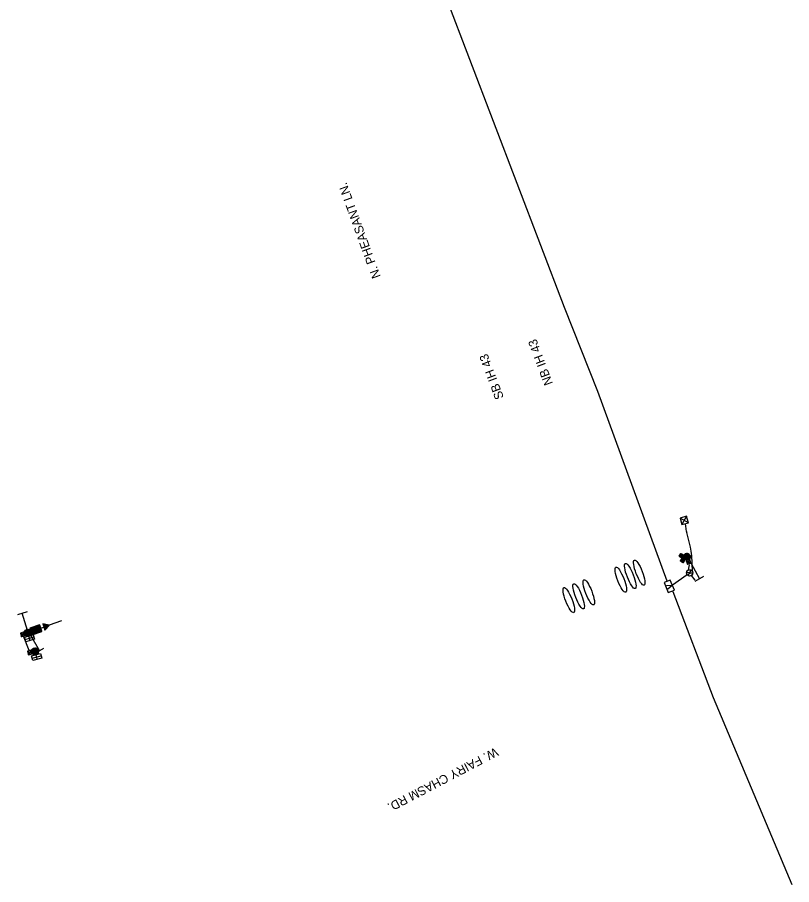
# Model space of a CAD drawing. Extents: x 601562 to 605316, y 332050 to 402250.
# Drawn here: x 602135 to 603050, y 352481 to 353507 of the extents above; entities that cross this region are included whole.
import ezdxf

# ---------------------------------------------------------------- set-up
doc = ezdxf.new("R2010")
doc.units = 0
doc.layers.add('P_FTMS', color=7, linetype='Continuous')
doc.layers.add('P_FTMSConduit', color=7, linetype='Continuous')

# ---------------------------------------------------------------- blocks, each defined once
blk = doc.blocks.new('FTMS_FCV')
at = {"layer": 'P_FTMS'}
blk.add_line((12.7, 16.3), (0.6, -21.9), dxfattribs=at)
blk.add_lwpolyline([(39.1, 24.4), (-39.1, 24.4), (-39.1, -24.4), (39.1, -24.4)], close=True, dxfattribs=at)
blk.add_lwpolyline([(-12.1, 16.2), (0.6, -21.9)], dxfattribs=at)
blk = doc.blocks.new('FMB')
at = {"layer": 'P_FTMS'}
for p, q in [((24, -24), (-24, 24)), ((-24, -24), (24, 24))]:
    blk.add_line(p, q, dxfattribs=at)
blk.add_lwpolyline([(24, -24), (24, 24), (-24, 24), (-24, -24)], close=True, dxfattribs=at)
blk = doc.blocks.new('_U255')
at = {"layer": 'P_FTMS'}
for points in [[(-14.7, -7), (7, -14.7), (0, 0)], [(14.7, 7), (-7, 14.7), (0, 0)]]:
    blk.add_lwpolyline(points, close=True, dxfattribs=at)
at = {"layer": 'P_FTMS', "xscale": 0.4713263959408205, "yscale": 0.4713263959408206, "rotation": 70.39802054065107}
blk.add_blockref('FMB', (0, 0), dxfattribs=at)
blk = doc.blocks.new('FTMS_FERA')
at = {"layer": 'P_FTMS'}
for p, q in [((-65.1, 36.6), (-65.1, -36.6)), ((65.1, 0), (-65.1, 0))]:
    blk.add_line(p, q, dxfattribs=at)
blk = doc.blocks.new('FMD')
at = {"layer": 'P_FTMS'}
for p, q in [((16.9, 17.6), (-16.9, 17.6)), ((-16.1, 16.1), (-16.1, 18.4)), ((16.1, 16.1), (-16.1, 16.1)), ((15.5, 19), (-15.5, 19)), ((-14.6, 14.6), (-14.6, 19.9)), ((14.6, 14.6), (-14.6, 14.6)), ((14, 20.5), (-14, 20.5)), ((-13.2, 13.2), (-13.2, 21.3)), ((13.2, 13.2), (-13.2, 13.2)), ((12.5, 21.9), (-12.5, 21.9)), ((-11.7, 11.7), (-11.7, 22.8)), ((11.7, 11.7), (-11.7, 11.7)), ((11.1, 23.4), (-11.1, 23.4)), ((-10.2, 10.2), (-10.2, 24.2)), ((10.2, 10.2), (-10.2, 10.2)), ((9.6, 24.9), (-9.6, 24.9)), ((-8.8, 8.8), (-8.8, 25.7)), ((8.8, 8.8), (-8.8, 8.8)), ((8.2, 26.3), (-8.2, 26.3)), ((-7.3, 7.3), (-7.3, 27.2)), ((7.3, 7.3), (-7.3, 7.3)), ((6.7, 27.8), (-6.7, 27.8)), ((-5.9, 5.9), (-5.9, 28.6)), ((5.9, 5.9), (-5.9, 5.9)), ((5.2, 29.3), (-5.2, 29.3)), ((-4.4, 4.4), (-4.4, 30.1)), ((4.4, 4.4), (-4.4, 4.4)), ((3.8, 30.7), (-3.8, 30.7)), ((-2.9, 2.9), (-2.9, 31.6)), ((2.9, 2.9), (-2.9, 2.9)), ((2.3, 32.2), (-2.3, 32.2)), ((-1.5, 1.5), (-1.5, 33)), ((1.5, 1.5), (-1.5, 1.5)), ((0.8, 33.6), (-0.8, 33.6)), ((0, 0), (0, 34.5)), ((1.5, 1.5), (1.5, 33)), ((2.9, 2.9), (2.9, 31.6)), ((4.4, 4.4), (4.4, 30.1)), ((5.9, 5.9), (5.9, 28.6)), ((7.3, 7.3), (7.3, 27.2)), ((8.8, 8.8), (8.8, 25.7)), ((10.2, 10.2), (10.2, 24.2)), ((11.7, 11.7), (11.7, 22.8)), ((13.2, 13.2), (13.2, 21.3)), ((14.6, 14.6), (14.6, 19.9)), ((16.1, 16.1), (16.1, 18.4))]:
    blk.add_line(p, q, dxfattribs=at)
blk.add_lwpolyline([(-17.2, 17.2), (0, 34.5), (17.2, 17.2), (0, 0)], close=True, dxfattribs=at)
blk = doc.blocks.new('FMB_1')
at = {"layer": 'P_FTMS'}
for p, q in [((24.4, -24.4), (-24.4, 24.4)), ((-24.4, -24.4), (24.4, 24.4))]:
    blk.add_line(p, q, dxfattribs=at)
blk.add_lwpolyline([(24.4, -24.4), (24.4, 24.4), (-24.4, 24.4), (-24.4, -24.4)], close=True, dxfattribs=at)

msp = doc.modelspace()

# ---------------------------------------------------------------- linework, layer by layer
at = {"layer": 'P_FTMS'}
for p, q in [((602922.6, 352868.1), (602924.6, 352871.9)), ((602922.6, 352868.6), (602924.2, 352871.6)), ((602922.7, 352867.3), (602925.3, 352872.2)), ((602922.7, 352867.7), (602925, 352872.1)), ((602922.7, 352869.2), (602923.7, 352871.2)), ((602922.9, 352867), (602925.6, 352872.3)), ((602923, 352866.7), (602925.9, 352872.4)), ((602923.1, 352866.5), (602926.2, 352872.4)), ((602923.2, 352866.2), (602926.5, 352872.4)), ((602923.4, 352866), (602926.8, 352872.4)), ((602923.6, 352865.8), (602927, 352872.4)), ((602923.7, 352865.6), (602927.3, 352872.3)), ((602930.5, 352867.7), (602923.8, 352871.2)), ((602923.9, 352865.4), (602927.5, 352872.3)), ((602930.5, 352868), (602924, 352871.4)), ((602924.1, 352865.3), (602927.8, 352872.2)), ((602930.6, 352868.2), (602924.2, 352871.6)), ((602924.3, 352865.1), (602928, 352872.1)), ((602930.6, 352868.5), (602924.4, 352871.7)), ((602924.5, 352865), (602928.2, 352872)), ((602930.5, 352868.8), (602924.6, 352871.9)), ((602924.7, 352864.9), (602928.4, 352871.9)), ((602930.5, 352869), (602924.9, 352872)), ((602924.9, 352864.8), (602928.7, 352871.8)), ((602930.5, 352869.4), (602925.2, 352872.1)), ((602925.2, 352864.7), (602928.8, 352871.7)), ((602925.4, 352864.6), (602929, 352871.5)), ((602930.4, 352869.7), (602925.5, 352872.2)), ((602925.6, 352864.5), (602929.2, 352871.4)), ((602930.2, 352870), (602925.8, 352872.3)), ((602925.9, 352864.5), (602929.4, 352871.2)), ((602930.1, 352870.4), (602926.2, 352872.4)), ((602929.8, 352870.8), (602926.7, 352872.4)), ((602929.3, 352871.3), (602927.4, 352872.3)), ((602929.2, 352865.4), (602922.6, 352868.9)), ((602929, 352865.2), (602922.6, 352868.6)), ((602928.8, 352865.1), (602922.6, 352868.3)), ((602928.5, 352864.9), (602922.6, 352868.1)), ((602928.3, 352864.8), (602922.6, 352867.8)), ((602929.6, 352865.8), (602922.7, 352869.4)), ((602929.4, 352865.6), (602922.7, 352869.1)), ((602928, 352864.7), (602922.7, 352867.5)), ((602929.7, 352865.9), (602922.8, 352869.6)), ((602927.7, 352864.6), (602922.8, 352867.1)), ((602930, 352866.3), (602922.9, 352870.1)), ((602929.9, 352866.1), (602922.9, 352869.8)), ((602927.3, 352864.5), (602922.9, 352866.8)), ((602930.1, 352866.6), (602923.1, 352870.3)), ((602926.9, 352864.4), (602923.1, 352866.4)), ((602930.2, 352866.8), (602923.2, 352870.5)), ((602930.3, 352867), (602923.3, 352870.7)), ((602930.4, 352867.2), (602923.4, 352870.9)), ((602926.4, 352864.4), (602923.4, 352866)), ((602930.4, 352867.5), (602923.6, 352871.1)), ((602925.7, 352864.5), (602923.8, 352865.5)), ((602926.1, 352864.4), (602929.6, 352871)), ((602926.4, 352864.4), (602929.8, 352870.8)), ((602926.6, 352864.4), (602929.9, 352870.6)), ((602926.9, 352864.4), (602930.1, 352870.4)), ((602927.2, 352864.5), (602930.2, 352870.1)), ((602927.5, 352864.5), (602930.3, 352869.8)), ((602927.8, 352864.6), (602930.4, 352869.5)), ((602928.2, 352864.8), (602930.5, 352869.2)), ((602928.5, 352864.9), (602930.6, 352868.7)), ((602929, 352865.2), (602930.6, 352868.3)), ((602929.5, 352865.7), (602930.5, 352867.6)), ((602186.8, 352792.7), (602172.4, 352787.6)), ((602145, 352782.1), (602143.1, 352778.2)), ((602144.6, 352781.8), (602143.1, 352778.7)), ((602144.1, 352781.3), (602143.1, 352779.4)), ((602143.1, 352779.2), (602150, 352776)), ((602143.1, 352779), (602149.8, 352775.8)), ((602145.3, 352782.3), (602143.2, 352777.8)), ((602143.2, 352779.7), (602150.3, 352776.3)), ((602143.2, 352779.5), (602150.1, 352776.1)), ((602145.7, 352782.4), (602143.3, 352777.4)), ((602143.3, 352780), (602150.4, 352776.5)), ((602146, 352782.5), (602143.4, 352777.1)), ((602143.4, 352780.2), (602150.6, 352776.7)), ((602146.3, 352782.6), (602143.5, 352776.8)), ((602143.5, 352780.4), (602150.7, 352777)), ((602143.6, 352780.6), (602150.8, 352777.2)), ((602146.6, 352782.6), (602143.7, 352776.6)), ((602143.7, 352780.8), (602150.8, 352777.4)), ((602146.8, 352782.7), (602143.8, 352776.4)), ((602143.8, 352781), (602150.9, 352777.6)), ((602147.1, 352782.7), (602144, 352776.1)), ((602144, 352781.2), (602151, 352777.9)), ((602147.4, 352782.7), (602144.2, 352775.9)), ((602144.2, 352781.4), (602151, 352778.1)), ((602147.6, 352782.6), (602144.3, 352775.8)), ((602144.3, 352781.6), (602151, 352778.4)), ((602147.9, 352782.6), (602144.5, 352775.6)), ((602144.5, 352781.8), (602151.1, 352778.6)), ((602148.1, 352782.5), (602144.7, 352775.5)), ((602144.7, 352781.9), (602151, 352778.9)), ((602148.3, 352782.5), (602144.9, 352775.3)), ((602145, 352782.1), (602151, 352779.2)), ((602148.6, 352782.4), (602145.1, 352775.2)), ((602145.2, 352782.2), (602151, 352779.5)), ((602148.8, 352782.3), (602145.3, 352775.1)), ((602145.5, 352782.4), (602150.9, 352779.8)), ((602149, 352782.2), (602145.6, 352775)), ((602145.8, 352782.5), (602150.8, 352780.1)), ((602149.2, 352782), (602145.8, 352774.9)), ((602149.4, 352781.9), (602146, 352774.8)), ((602146.2, 352782.6), (602150.7, 352780.4)), ((602149.6, 352781.8), (602146.3, 352774.8)), ((602149.8, 352781.6), (602146.5, 352774.7)), ((602146.6, 352782.6), (602150.5, 352780.8)), ((602150, 352781.4), (602146.8, 352774.7)), ((602150.1, 352781.2), (602147, 352774.7)), ((602147.1, 352782.7), (602150.2, 352781.2)), ((602150.3, 352781), (602147.3, 352774.7)), ((602150.5, 352780.8), (602147.6, 352774.7)), ((602147.8, 352782.6), (602149.7, 352781.7)), ((602150.6, 352780.5), (602147.9, 352774.8)), ((602150.7, 352780.2), (602148.2, 352774.8)), ((602150.9, 352779.9), (602148.5, 352774.9)), ((602151, 352779.6), (602148.8, 352775.1)), ((602151, 352779.2), (602149.2, 352775.3)), ((602149.6, 352783.8), (602149.6, 352783.7)), ((602149.6, 352783.8), (602159.8, 352778.9)), ((602149.6, 352783.6), (602159.5, 352778.8)), ((602149.9, 352783.9), (602149.7, 352783.3)), ((602149.7, 352783.3), (602159.2, 352778.7)), ((602150.3, 352784), (602149.8, 352783)), ((602149.8, 352782.9), (602158.9, 352778.6)), ((602150.6, 352784.2), (602149.9, 352782.7)), ((602149.9, 352783.9), (602160.1, 352779)), ((602149.9, 352782.6), (602158.5, 352778.5)), ((602150.9, 352784.3), (602150, 352782.4)), ((602150, 352782.3), (602158.2, 352778.4)), ((602151.2, 352784.4), (602150.1, 352782.1)), ((602150.1, 352782), (602157.9, 352778.3)), ((602151.5, 352784.5), (602150.2, 352781.7)), ((602151.9, 352784.6), (602150.3, 352781.4)), ((602150.3, 352784), (602160.5, 352779.2)), ((602150.3, 352781.7), (602157.6, 352778.1)), ((602150.4, 352781.3), (602157.3, 352778)), ((602152.2, 352784.7), (602150.5, 352781.1)), ((602150.5, 352781), (602156.9, 352777.9)), ((602152.5, 352784.8), (602150.6, 352780.8)), ((602150.6, 352784.2), (602160.8, 352779.3)), ((602150.6, 352780.7), (602156.6, 352777.8)), ((602152.8, 352784.9), (602150.7, 352780.5)), ((602150.7, 352780.4), (602156.3, 352777.7)), ((602153.1, 352785.1), (602150.8, 352780.1)), ((602150.8, 352780.1), (602156, 352777.6)), ((602153.5, 352785.2), (602150.9, 352779.8)), ((602150.9, 352784.3), (602161.1, 352779.4)), ((602150.9, 352779.7), (602155.7, 352777.5)), ((602153.8, 352785.3), (602151, 352779.5)), ((602154.1, 352785.4), (602151.1, 352779.2)), ((602151.1, 352779.4), (602155.3, 352777.4)), ((602154.4, 352785.5), (602151.2, 352778.9)), ((602151.2, 352784.4), (602161.4, 352779.5)), ((602151.2, 352779.1), (602155, 352777.2)), ((602154.7, 352785.6), (602151.4, 352778.5)), ((602155.1, 352785.7), (602151.5, 352778.2)), ((602151.5, 352784.5), (602161.8, 352779.6)), ((602155.4, 352785.8), (602151.6, 352777.9)), ((602155.7, 352786), (602151.7, 352777.6)), ((602156, 352786.1), (602151.8, 352777.3)), ((602156.3, 352786.2), (602151.9, 352776.9)), ((602151.9, 352784.6), (602162.1, 352779.7)), ((602156.7, 352786.3), (602152, 352776.6)), ((602157, 352786.4), (602152.1, 352776.3)), ((602152.2, 352784.7), (602162.4, 352779.8)), ((602157.3, 352786.5), (602152.4, 352776.3)), ((602152.5, 352784.8), (602162.7, 352779.9)), ((602157.6, 352786.6), (602152.7, 352776.4)), ((602152.8, 352784.9), (602163, 352780.1)), ((602157.9, 352786.8), (602153.1, 352776.5)), ((602153.1, 352785.1), (602163.4, 352780.2)), ((602158.3, 352786.9), (602153.4, 352776.7)), ((602153.5, 352785.2), (602163.4, 352780.4)), ((602158.6, 352787), (602153.7, 352776.8)), ((602153.8, 352785.3), (602163.3, 352780.7)), ((602158.9, 352787.1), (602154, 352776.9)), ((602154.1, 352785.4), (602163.2, 352781)), ((602159.2, 352787.2), (602154.3, 352777)), ((602154.4, 352785.5), (602163.1, 352781.4)), ((602159.5, 352787.3), (602154.7, 352777.1)), ((602154.7, 352785.6), (602163, 352781.7)), ((602159.9, 352787.4), (602155, 352777.2)), ((602155.1, 352785.7), (602162.9, 352782)), ((602155.3, 352781.6), (602155.1, 352781.5)), ((602160.2, 352787.5), (602155.3, 352777.3)), ((602155.3, 352781.6), (602155.3, 352781.6)), ((602155.4, 352785.8), (602162.7, 352782.3)), ((602160.5, 352787.7), (602155.6, 352777.4)), ((602155.7, 352786), (602162.6, 352782.6)), ((602160.8, 352787.8), (602155.9, 352777.6)), ((602156, 352786.1), (602162.5, 352783)), ((602160.9, 352787.4), (602156.3, 352777.7)), ((602156.3, 352786.2), (602162.4, 352783.3)), ((602161.1, 352787.1), (602156.6, 352777.8)), ((602156.7, 352786.3), (602162.3, 352783.6)), ((602161.2, 352786.8), (602156.9, 352777.9)), ((602157, 352786.4), (602162.2, 352783.9)), ((602161.3, 352786.5), (602157.2, 352778)), ((602157.3, 352786.5), (602162.1, 352784.2)), ((602161.4, 352786.2), (602157.5, 352778.1)), ((602157.6, 352786.6), (602162, 352784.6)), ((602157.9, 352786.8), (602161.8, 352784.9)), ((602161.5, 352785.8), (602157.9, 352778.2)), ((602161.6, 352785.5), (602158.2, 352778.4)), ((602158.3, 352786.9), (602161.7, 352785.2)), ((602161.7, 352785.2), (602158.5, 352778.5)), ((602158.6, 352787), (602161.6, 352785.5)), ((602161.8, 352784.9), (602158.8, 352778.6)), ((602158.9, 352787.1), (602161.5, 352785.8)), ((602162, 352784.6), (602159.1, 352778.7)), ((602159.2, 352787.2), (602161.4, 352786.2)), ((602159.5, 352787.3), (602161.3, 352786.5)), ((602162.1, 352784.2), (602159.5, 352778.8)), ((602162.2, 352783.9), (602159.8, 352778.9)), ((602159.9, 352787.4), (602161.2, 352786.8)), ((602162.3, 352783.6), (602160.1, 352779)), ((602160.2, 352787.5), (602161.1, 352787.1)), ((602162.4, 352783.3), (602160.4, 352779.1)), ((602160.5, 352787.7), (602160.9, 352787.4)), ((602162.5, 352783), (602160.7, 352779.3)), ((602162.6, 352782.6), (602161.1, 352779.4)), ((602162.7, 352782.3), (602161.4, 352779.5)), ((602162.9, 352782), (602161.7, 352779.6)), ((602163, 352781.7), (602162, 352779.7)), ((602162.2, 352784), (602165.9, 352785.3)), ((602163.1, 352781.4), (602162.3, 352779.8)), ((602163.2, 352781), (602162.7, 352779.9)), ((602163.3, 352780.7), (602163, 352780)), ((602163.4, 352780.4), (602163.3, 352780.2)), ((602164.6, 352789.1), (602164.6, 352789.1)), ((602164.6, 352789), (602171, 352785.9)), ((602164.9, 352789), (602164.7, 352788.8)), ((602165.1, 352789), (602164.8, 352788.4)), ((602164.8, 352788.6), (602170.8, 352785.7)), ((602165.3, 352789), (602164.9, 352788.1)), ((602164.9, 352788.3), (602170.6, 352785.6)), ((602165, 352788), (602170.5, 352785.4)), ((602165.1, 352789), (602171.1, 352786.1)), ((602165.6, 352788.9), (602165.1, 352787.8)), ((602165.1, 352787.7), (602170.3, 352785.2)), ((602165.8, 352788.9), (602165.2, 352787.5)), ((602165.2, 352787.4), (602170.2, 352785)), ((602166.1, 352788.8), (602165.3, 352787.2)), ((602165.3, 352787), (602170, 352784.8)), ((602166.3, 352788.8), (602165.4, 352786.8)), ((602165.4, 352786.7), (602169.8, 352784.6)), ((602166.6, 352788.7), (602165.5, 352786.5)), ((602166.8, 352788.7), (602165.6, 352786.2)), ((602165.6, 352786.4), (602169.7, 352784.4)), ((602167.1, 352788.6), (602165.7, 352785.9)), ((602165.7, 352786.1), (602169.5, 352784.2)), ((602167.3, 352788.6), (602165.8, 352785.6)), ((602165.8, 352785.8), (602169.4, 352784)), ((602165.9, 352785.4), (602169.2, 352783.9)), ((602166, 352788.8), (602171.3, 352786.3)), ((602167.5, 352788.5), (602166, 352785.2)), ((602166, 352785.1), (602169, 352783.7)), ((602167.8, 352788.5), (602166.1, 352784.9)), ((602166.1, 352784.8), (602168.9, 352783.5)), ((602168, 352788.5), (602166.2, 352784.6)), ((602166.2, 352784.5), (602168.7, 352783.3)), ((602168.3, 352788.4), (602166.3, 352784.3)), ((602166.3, 352784.2), (602168.5, 352783.1)), ((602168.5, 352788.4), (602166.4, 352784)), ((602168.8, 352788.3), (602166.5, 352783.6)), ((602166.5, 352783.8), (602168.4, 352782.9)), ((602169, 352788.3), (602166.6, 352783.3)), ((602166.6, 352783.5), (602168.2, 352782.7)), ((602169.3, 352788.2), (602166.7, 352783)), ((602166.7, 352783.2), (602168.1, 352782.5)), ((602166.8, 352782.9), (602167.9, 352782.3)), ((602169.5, 352788.2), (602166.9, 352782.7)), ((602166.9, 352782.6), (602167.7, 352782.2)), ((602167, 352788.7), (602171.5, 352786.5)), ((602169.7, 352788.1), (602167, 352782.4)), ((602167, 352782.2), (602167.6, 352782)), ((602170, 352788.1), (602167.1, 352782)), ((602167.1, 352781.9), (602167.4, 352781.8)), ((602170.2, 352788), (602167.2, 352781.7)), ((602167.2, 352781.6), (602167.3, 352781.6)), ((602170.5, 352788), (602167.6, 352782)), ((602167.9, 352788.5), (602171.6, 352786.7)), ((602170.7, 352788), (602168.2, 352782.7)), ((602168.8, 352788.3), (602171.8, 352786.9)), ((602171, 352787.9), (602168.8, 352783.4)), ((602171.2, 352787.9), (602169.4, 352784.1)), ((602169.7, 352788.1), (602171.9, 352787.1)), ((602171.4, 352787.8), (602170, 352784.8)), ((602170.6, 352788), (602172.1, 352787.3)), ((602171.7, 352787.8), (602170.6, 352785.5)), ((602171.9, 352787.7), (602171.2, 352786.2)), ((602171.5, 352787.8), (602172.3, 352787.4)), ((602172.2, 352787.7), (602171.8, 352786.9)), ((602172.4, 352787.6), (602172.4, 352787.6)), ((602143.1, 352778.7), (602149.6, 352775.6)), ((602143.1, 352778.5), (602149.4, 352775.4)), ((602143.1, 352778.2), (602149.2, 352775.3)), ((602143.1, 352777.9), (602148.9, 352775.1)), ((602143.2, 352777.6), (602148.6, 352775)), ((602143.3, 352777.3), (602148.3, 352774.9)), ((602143.5, 352776.9), (602148, 352774.8)), ((602143.7, 352776.6), (602147.6, 352774.7)), ((602143.7, 352770.6), (602154.1, 352773.6)), ((602144, 352776.2), (602147.1, 352774.7)), ((602144.4, 352775.7), (602146.4, 352774.7)), ((602149.7, 352769.3), (602148.2, 352774.8)), ((602151.1, 352778.7), (602149.6, 352775.6)), ((602151, 352778), (602150.1, 352776)), ((602151.3, 352778.8), (602154.7, 352777.1)), ((602151.4, 352778.5), (602154.4, 352777)), ((602151.5, 352778.1), (602154.1, 352776.9)), ((602151.6, 352777.8), (602153.7, 352776.8)), ((602151.7, 352777.5), (602153.4, 352776.7)), ((602151.8, 352777.2), (602153.1, 352776.6)), ((602152, 352776.9), (602152.8, 352776.5)), ((602152.1, 352776.5), (602152.5, 352776.3)), ((602158.4, 352759.2), (602151.5, 352757)), ((602158.6, 352759), (602151.5, 352756.7)), ((602158.7, 352758.8), (602151.5, 352756.5)), ((602158.9, 352758.6), (602151.5, 352756.2)), ((602159, 352758.4), (602151.5, 352756)), ((602158, 352759.6), (602151.6, 352757.5)), ((602158.2, 352759.4), (602151.6, 352757.2)), ((602157.8, 352759.8), (602151.7, 352757.8)), ((602157.5, 352759.9), (602151.8, 352758.1)), ((602157.2, 352760.1), (602152, 352758.4)), ((602152, 352758.5), (602153.9, 352752.8)), ((602156.9, 352760.2), (602152.1, 352758.7)), ((602152.2, 352758.8), (602154.2, 352752.7)), ((602156.5, 352760.4), (602152.4, 352759)), ((602152.4, 352759), (602154.4, 352752.6)), ((602152.6, 352759.2), (602154.7, 352752.6)), ((602156, 352760.4), (602152.7, 352759.4)), ((602152.8, 352759.4), (602155, 352752.5)), ((602153, 352759.6), (602155.2, 352752.5)), ((602153.2, 352759.8), (602155.5, 352752.5)), ((602155.3, 352760.5), (602153.3, 352759.8)), ((602153.4, 352759.9), (602155.7, 352752.5)), ((602153.6, 352760), (602156, 352752.5)), ((602153.8, 352760.1), (602156.2, 352752.6)), ((602154, 352760.2), (602156.5, 352752.6)), ((602154.2, 352760.3), (602156.7, 352752.7)), ((602154.5, 352760.4), (602156.9, 352752.8)), ((602154.7, 352760.4), (602157.1, 352752.9)), ((602154.9, 352760.5), (602157.4, 352753)), ((602155.2, 352760.5), (602157.6, 352753.1)), ((602155.4, 352760.5), (602157.8, 352753.2)), ((602155.7, 352760.5), (602158, 352753.4)), ((602156, 352760.5), (602158.2, 352753.6)), ((602156.2, 352760.4), (602158.4, 352753.8)), ((602156.5, 352760.4), (602158.6, 352754)), ((602156.8, 352760.3), (602158.7, 352754.2)), ((602157.1, 352760.2), (602158.9, 352754.5)), ((602157.4, 352760), (602159.1, 352754.8)), ((602157.7, 352759.8), (602159.2, 352755.1)), ((602158, 352759.6), (602159.3, 352755.5)), ((602158.4, 352759.2), (602159.4, 352756)), ((602158.8, 352758.7), (602159.5, 352756.6)), ((602151.5, 352757), (602152.6, 352753.7)), ((602151.5, 352756.3), (602152.2, 352754.3)), ((602159.1, 352758.2), (602151.6, 352755.7)), ((602159.2, 352757.9), (602151.6, 352755.5)), ((602151.6, 352757.5), (602152.9, 352753.4)), ((602151.7, 352757.9), (602153.3, 352753.2)), ((602159.3, 352757.7), (602151.7, 352755.3)), ((602159.3, 352757.5), (602151.7, 352755)), ((602159.4, 352757.3), (602151.8, 352754.8)), ((602151.9, 352758.2), (602153.6, 352753)), ((602159.4, 352757), (602152, 352754.6)), ((602159.4, 352756.8), (602152.1, 352754.4)), ((602159.5, 352756.5), (602152.2, 352754.2)), ((602152.2, 352748.5), (602162.6, 352751.4)), ((602159.4, 352756.3), (602152.4, 352754)), ((602159.4, 352756), (602152.5, 352753.8)), ((602159.4, 352755.7), (602152.7, 352753.6)), ((602159.3, 352755.5), (602152.9, 352753.4)), ((602159.2, 352755.2), (602153.2, 352753.2)), ((602159.1, 352754.9), (602153.4, 352753.1)), ((602159, 352754.6), (602153.7, 352752.9)), ((602158.8, 352754.3), (602154.1, 352752.8)), ((602158.6, 352754), (602154.5, 352752.6)), ((602158.2, 352753.6), (602154.9, 352752.5)), ((602157.7, 352753.2), (602155.6, 352752.5)), ((602158.2, 352747.2), (602156.7, 352752.7))]:
    msp.add_line(p, q, dxfattribs=at)
for points in [[(602152.2, 352776.2), (602163.5, 352780.2), (602160.8, 352787.8), (602149.5, 352783.8)], [(602164.6, 352789.1), (602167.2, 352781.6), (602172.4, 352787.6)], [(602144.5, 352767.9), (602142.9, 352773.4), (602153.4, 352776.3), (602154.9, 352770.8)], [(602153, 352745.7), (602151.4, 352751.2), (602161.9, 352754.2), (602163.4, 352748.6)]]:
    msp.add_lwpolyline(points, close=True, dxfattribs=at)
for centre, radius in [((602926.6, 352868.4), 4), ((602929.8, 352849.4), 3.75), ((602147.1, 352778.7), 4), ((602155.5, 352756.5), 4)]:
    msp.add_circle(centre, radius, dxfattribs=at)
for centre, start, end in [((602928, 352853.6), 240.5454, 346.8011), ((602931.6, 352845.3), 60.5454, 166.8011)]:
    msp.add_arc(centre, 3.75, start, end, dxfattribs=at)
for centre in [(602859.6, 352845.7), (602870.2, 352849.7), (602848.4, 352841.3), (602810.5, 352826.4), (602786.9, 352817.2), (602798.5, 352821.7)]:
    msp.add_ellipse(centre, major_axis=(-5.8, 14.9), ratio=0.23471, dxfattribs=at)
at = {"layer": 'P_FTMSConduit'}
for p, q in [((602781.7, 353163.1), (602612.7, 353607.2)), ((602821.3, 353064), (602781.7, 353163.1)), ((602903.2, 352839.5), (602821.3, 353064)), ((602926.2, 352898.4), (602925, 352907.7)), ((602930.8, 352879.9), (602926.4, 352897.2)), ((602933, 352851.5), (602932.2, 352869.9)), ((602928.6, 352853), (602929.6, 352858.8)), ((602909.4, 352835.1), (602926.7, 352847.3)), ((602936.5, 352840.6), (602931.8, 352846.3)), ((602909.8, 352827.4), (602957.6, 352701.8)), ((602148.8, 352757.4), (602141.8, 352774.6)), ((602957.5, 352702), (603050.5, 352480.6))]:
    msp.add_line(p, q, dxfattribs=at)
for centre, radius, start, end in [((602936.1, 352899.7), 10, 187.1797, 194.1363), ((602882.3, 352867.7), 50, 2.4924, 14.1363)]:
    msp.add_arc(centre, radius, start, end, dxfattribs=at)

# ---------------------------------------------------------------- block references
at = {"layer": 'P_FTMS'}
for name, p, xscale, yscale, rotation in [('FMB_1', (602923.4, 352911.4), 0.16404166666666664, 0.16404166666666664, 104.77675238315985), ('FMD', (602917.5, 352869), 0.16404166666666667, 0.1640416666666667, -76.04477593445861), ('FMD', (602918.8, 352863.5), 0.16404166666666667, 0.1640416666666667, -76.04477593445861), ('_U255', (602928.5, 352862.4), 0.19684999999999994, 0.1968499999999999, -142.16323950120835), ('FTMS_FERA', (602936.3, 352851.8), 0.1640416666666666, 0.1640416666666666, 118.63955569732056), ('FTMS_FCV', (602905.7, 352833.5), 0.16404166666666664, 0.1640416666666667, 112.41478162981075), ('FTMS_FERA', (602143.5, 352791.4), 0.16404166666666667, 0.16404166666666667, -73.23242705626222), ('_U255', (602141.1, 352776.8), 0.19684999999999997, 0.19685, 128.05887942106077), ('FTMS_FERA', (602155.4, 352766.5), 0.16404166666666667, 0.16404166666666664, 120.32823896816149), ('_U255', (602149.4, 352755.2), 0.19684999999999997, 0.19684999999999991, 123.4112964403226)]:
    msp.add_blockref(name, p, dxfattribs=dict(at, xscale=xscale, yscale=yscale, rotation=rotation))

# ---------------------------------------------------------------- texts
at = {"layer": 'P_FTMSConduit'}
for s, rotation, p in [('N. PHEASANT LN.', 109.9406, (602564.5, 353199.9)), ('NB IH 43', 110.5095, (602768.2, 353073.5)), ('SB IH 43', 110.5095, (602710.2, 353056.8)), ('W. FAIRY CHASM RD.', 207.705, (602699.7, 352643.1))]:
    msp.add_text(s, height=10.5, rotation=rotation, dxfattribs=at).set_placement(p)

doc.saveas('drawing.dxf')
